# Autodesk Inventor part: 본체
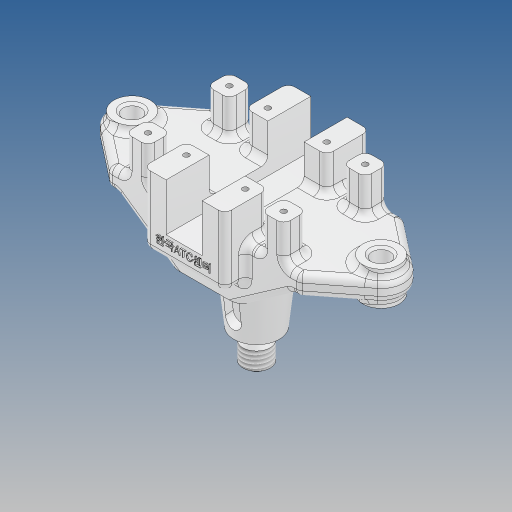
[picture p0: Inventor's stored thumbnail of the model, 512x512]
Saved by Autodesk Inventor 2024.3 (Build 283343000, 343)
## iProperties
Created: 2025-07
Part Number: 본체
Material: 알루미늄 6061
Document SubType Name: Modeling
Designer: user
Mass: 327.756 g
Surface Area: 261.455 cm^2
Volume: 121.391 cm^3
Density: 2.7 g/cm^3
Appearance: 알루미늄 - 평지
Author: user
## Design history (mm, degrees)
sketch "스케치1"
  geometry: L1 (-41.804, 23)-(41.804, 23); L2 (41.804, 23)-(41.804, -23); L3 (41.804, -23)-(-41.804, -23); L4 (-41.804, -23)-(-41.804, 23); L5 (-41.804, 23)-(41.804, -23); L6 (41.804, 23)-(-41.804, -23); L7 (41.804, -23)-(61.157, -7.88); L8 (41.804, 23)-(61.157, 7.88); L9 (0, -32.2)-(0, 32.2) reference; L10 (-41.804, -23)-(-61.157, -7.88); L11 (-41.804, 23)-(-61.157, 7.88); C1 r 10 at (55, 0); C2 r 8 at (55, 0); C3 r 8 at (-55, 0); A1 r 10 centre (-55, 0) between (-61.157, -7.88) and (-61.157, 7.88); 4 further points
  constraints: 20 end point, 4 centre point, 4 symmetric about line, 2 coincident, 2 midpoint, 2 parallel, 2 point on circle, 2 tangent, 1 horizontal, 1 horizontal alignment, 1 perpendicular, 1 other
  dimensions: "d0" = 110 distance of A1.centre C1.centre; "d1" = 46 distance between parallel lines of L1 L3; "d2" = 20 diameter of C1; "d3" = 76 deg angle of L8 L7; "d6" = 16 diameter of C2; "d7" = 16 diameter of C3
extrude "돌출1" new body sketch "스케치1" stored distance "d4" = 9; taper "d5" = 0 deg
extrude "돌출2" join sketch "스케치1" stored distance "d8" = 15; taper "d9" = 0 deg
sketch "스케치2"
  geometry: L1 (-41.804, -23)-(41.804, -23) reference; L2 (41.804, 23)-(-41.804, 23) reference; L3 (-30, 18)-(30, 18); L4 (30, 18)-(30, -18); L5 (30, -18)-(-30, -18); L6 (-30, -18)-(-30, 18); L7 (-30, 18)-(30, -18); L8 (30, 18)-(-30, -18); L9 (-35, 23)-(-25, 23); L10 (-25, 23)-(-25, 13); L11 (-25, 13)-(-35, 13); L12 (-35, 13)-(-35, 23); L13 (-35, 23)-(-25, 13); L14 (-25, 23)-(-35, 13); L15 (-35, -13)-(-25, -13); L16 (-25, -13)-(-25, -23); L17 (-25, -23)-(-35, -23); L18 (-35, -23)-(-35, -13); L19 (-35, -13)-(-25, -23); L20 (-25, -13)-(-35, -23); L21 (25, -13)-(35, -13); L22 (35, -13)-(35, -23); L23 (35, -23)-(25, -23); L24 (25, -23)-(25, -13); L25 (25, -13)-(35, -23); L26 (35, -13)-(25, -23); L27 (25, 23)-(35, 23); L28 (35, 23)-(35, 13); L29 (35, 13)-(25, 13); L30 (25, 13)-(25, 23); L31 (25, 23)-(35, 13); L32 (35, 23)-(25, 13); 7 further points
  constraints: 60 end point, 10 midpoint, 10 parallel, 5 horizontal, 5 perpendicular, 2 point on line
  dimensions: "d10" = 60 distance between parallel lines of L4 L6; "d11" = 36 distance between parallel lines of L5 L3; "d12" = 10 distance between parallel lines of L10 L12; "d13" = 10 distance between parallel lines of L11 L2; "d14" = 10 distance between parallel lines of L16 L18; "d15" = 10 distance between parallel lines of L22 L24; "d16" = 10 distance between parallel lines of L28 L30; "d17" = 10 distance between parallel lines of L27 L29
extrude "돌출3" join sketch "스케치2" distance "d18" = 16; taper "d19" = 0 deg
sketch "스케치3"
  geometry: L1 (6.804, 25)-(16.804, 25) reference; L2 (83.608, 0)-(0, 0) reference; L3 (41.804, -16)-(25.804, -16); L4 (41.804, 0)-(41.804, -16); L5 (25.804, -16)-(2.954, 0); L6 (2.954, 0)-(41.804, 0); L7 (57.804, -16)-(80.654, 0); L8 (0, 0)-(83.608, 0); L9 (41.804, -16)-(57.804, -16); 2 further points
  constraints: 14 end point, 4 symmetric about line, 2 point on line, 1 collinear, 1 horizontal, 1 midpoint, 1 vertical
  dimensions: "d20" = 145 deg angle of L3 L5; "d21" = 41 distance between parallel lines of L3 L1; "d22" = 16 distance from line of L4 L3.end
extrude "돌출4" join sketch "스케치3" stored distance "d23" = 16; taper "d24" = 0 deg
node "작업 평면1"
sketch "스케치4"
  geometry: L1 (-16.804, 9)-(-66.804, 9) reference; L2 (-59.804, 25)-(-23.804, 25); L3 (-23.804, 25)-(-23.804, -6); L4 (-23.804, -6)-(-59.804, -6); L5 (-59.804, -6)-(-59.804, 25); L6 (-59.804, 25)-(-23.804, -6); L7 (-23.804, 25)-(-59.804, -6); L8 (-57.804, -16)-(-25.804, -16) reference; 2 further points
  constraints: 12 end point, 2 parallel, 1 horizontal, 1 midpoint, 1 perpendicular, 1 vertical alignment
  dimensions: "d25" = 36 distance between parallel lines of L3 L5; "d26" = 31 distance between parallel lines of L4 L2; "d112" = 10 distance between parallel lines of L8 L4
extrude "돌출5" join sketch "스케치4" stored distance "d27" = 64; taper "d28" = 0 deg
sketch "스케치5"
  geometry: L1 (-23.804, 25)-(-59.804, 25) reference; L2 (-49.804, 25)-(-33.804, 25); L3 (-33.804, 25)-(-33.804, 4); L4 (-33.804, 4)-(-49.804, 4); L5 (-49.804, 4)-(-49.804, 25); 3 further points
  constraints: 8 end point, 2 midpoint, 2 parallel, 1 horizontal, 1 perpendicular, 1 point on line
  dimensions: "d29" = 16 distance between parallel lines of L3 L5; "d30" = 21 distance between parallel lines of L4 L1
extrude "돌출6" cut sketch "스케치5" distance "d31" = 64; taper "d32" = 0 deg
sketch "스케치6"
  geometry: L1 (0, 31)-(-64, 31) reference; L2 (-9, 15)-(-55, 15) reference; L3 (-45, 31)-(-19, 31); L4 (-19, 31)-(-19, 15); L5 (-19, 15)-(-45, 15); L6 (-45, 15)-(-45, 31); 5 further points
  constraints: 8 end point, 2 midpoint, 2 parallel, 2 point on line, 1 coincident, 1 horizontal, 1 perpendicular
  dimensions: "d33" = 26 distance between parallel lines of L4 L6
extrude "돌출7" cut sketch "스케치6" stored distance "d34" = 64; taper "d35" = 0 deg
sketch "스케치7"
  geometry: C1 r 12.5 at (16, -23); 1 further point
  constraints: 1 centre point, 1 coincident
  dimensions: "d36" = 25 diameter of C1
extrude "돌출8" join sketch "스케치7" distance "d37" = 4; taper "d38" = 0 deg
sketch "스케치8"
  geometry: L1 (-12.5, -24.5)-(12.5, -24.5) reference; L2 (0, -24.5)-(0, -47.5); L3 (0, -47.5)-(-10, -47.5); L4 (-10, -47.5)-(-12.5, -24.5); 1 further point
  constraints: 6 end point, 1 midpoint, 1 perpendicular, 1 vertical
  dimensions: "d39" = 23 distance between parallel lines of L1 L3; "d41" = 20 diameter of L3.end L2
revolve "회전1" sketch "스케치8" stored, may be unused: angle "d42" = 360 deg
sketch "스케치9"
  geometry: C1 r 10 at (0, 0) reference; C2 r 4.7 at (0, 0)
  constraints: 1 centre point, 1 coincident
  dimensions: "d43" = 9.4 diameter of C2
extrude "돌출9" join sketch "스케치9" distance "d44" = 3; taper "d45" = 0 deg
sketch "스케치11"
  geometry: L1 (-4.7, -50.5)-(4.7, -50.5) reference; L2 (-4.7, -50.5)-(-6, -52.752); L3 (0, -61.5)-(0, -50.5); L4 (-6, -52.752)-(-6, -61.5); L5 (-6, -61.5)-(0, -61.5); 1 further point
  constraints: 8 end point, 1 midpoint, 1 perpendicular, 1 vertical, 1 vertical alignment
  dimensions: "d50" = 30 deg angle of L3 L2; "d53" = 12 diameter of L4 L3; "d54" = 11 distance between parallel lines of L1 L5
revolve "회전2" sketch "스케치11" stored, may be unused: angle "d55" = 90 deg
feature "스레드1" dims "d56" = 8.748, "d57" = 0
sketch "스케치14"
  geometry: C1 r 8 at (0, 0) reference; C2 r 8 at (110, 0) reference; 3 further points
  constraints: 2 coincident
hole "구멍1" sketch "스케치14" at (0, 0), (110, 0) diameter "d62" = 8; stored, may be unused: countersink angle "d66" = 90 deg, drill point angle "d68" = 118 deg; dims "d63" = 6, "d64" = 4, "d65" = 2, "d67" = 8
sketch "스케치15"
  geometry: L1 (-30, 18)-(30, 18); L2 (30, 18)-(30, -18); L3 (30, -18)-(-30, -18); L4 (-30, -18)-(-30, 18); L5 (-30, 18)-(30, -18); L6 (30, 18)-(-30, -18); L7 (-13, 18)-(13, 18); L8 (13, 18)-(13, -18); L9 (13, -18)-(-13, -18); L10 (-13, -18)-(-13, 18); L11 (-13, 18)-(13, -18); L12 (13, 18)-(-13, -18); 2 further points
  constraints: 24 end point, 4 midpoint, 4 parallel, 2 horizontal, 2 perpendicular, 1 coincident, 1 point on line
  dimensions: "d76" = 60 distance between parallel lines of L2 L4; "d77" = 36 distance between parallel lines of L3 L1; "d78" = 26 distance between parallel lines of L8 L10
hole "구멍2" sketch "스케치15" at (-30, 18), (-30, -18), (-13, -18), (13, -18), (30, -18), (30, 18), (13, 18), (-13, 18) diameter "d69" = 2.459; stored, may be unused: countersink angle "d73" = 90 deg, drill point angle "d75" = 118 deg; dims "d70" = 6, "d71" = 4, "d72" = 2, "d74" = 8
node "작업 평면2"
sketch "스케치17"
  geometry: L1 (19.5, -14)-(22, -37) reference; L2 (20.217, -20.597)-(24.194, -20.164); L3 (24.194, -20.164)-(23.815, -16.685); L4 (23.815, -16.685)-(19.839, -17.117); L5 (20.217, -20.597)-(19.839, -17.117); L6 (21.19, -29.544)-(25.166, -29.112); L7 (21.568, -33.023)-(25.544, -32.591); L8 (25.544, -32.591)-(25.166, -29.112); L9 (22, -37)-(42, -37) reference; 1 further point
  constraints: 14 end point, 6 perpendicular, 4 point on line, 1 collinear
  dimensions: "d79" = 7 diameter of L4 L2; "d80" = 7 diameter of L7 L6; "d81" = 16 distance between parallel lines of L7 L4; "d82" = 4 distance between parallel lines of L1 L3; "d83" = 4 distance between parallel lines of L1 L8; "d120" = 4 distance of L1.end L7.start
revolve "회전4" stored, may be unused: angle "d85" = 90 deg
revolve "회전5" stored, may be unused: angle "d86" = 90 deg
sketch "스케치18"
  geometry: L1 (20.217, -20.597)-(24.194, -20.164) reference; L2 (21.19, -29.544)-(25.166, -29.112) reference; L3 (19.5, -14)-(22, -37) reference; L4 (24.194, -20.164)-(25.166, -29.112); L5 (25.166, -29.112)-(21.19, -29.544); L6 (20.217, -20.597)-(21.19, -29.544); L7 (24.194, -20.164)-(20.217, -20.597); 1 further point
  constraints: 8 end point, 1 collinear, 1 perpendicular
extrude "돌출11" cut sketch "스케치18" stored distance "d87" = 7; taper "d88" = 0 deg
sketch "스케치19"
  geometry: L1 (-49.804, 25)-(-59.804, 25) reference; 2 further points
  constraints: 1 vertical alignment, 1 other
  dimensions: "d89" = 24 distance from line of L1 point (-41.804, 1)
fillet "모깎기1" dims "d90" = 3
fillet "모깎기2" dims "d91" = 3
fillet "모깎기3" dims "d92" = 3
fillet "모깎기4" dims "d93" = 3
fillet "모깎기5" dims "d94" = 3
fillet "모깎기6" dims "d95" = 3
fillet "모깎기7" dims "d96" = 3
fillet "모깎기8" dims "d97" = 3
fillet "모깎기9" dims "d98" = 3
fillet "모깎기10" dims "d99" = 3
fillet "모깎기12" dims "d101" = 3
fillet "모깎기13" dims "d102" = 3
fillet "모깎기14" dims "d103" = 3
fillet "모깎기16" dims "d105" = 3
fillet "모깎기17" dims "d106" = 3
fillet "모깎기18" dims "d107" = 3
fillet "모깎기19" dims "d108" = 3
fillet "모깎기20" dims "d109" = 3
feature "엠보싱1" dims "d110" = 0.5, "d111" = 0
node "작업 평면3"
sketch "스케치20"
  geometry: L1 (-22, -82)-(-34, -82) reference; L2 (-28, -20.5)-(-28, -82); L3 (-28, -82)-(-23.3, -82); L4 (-22, -81)-(-23.3, -82); L5 (-22, -81)-(-28, -81); L6 (-22, -82)-(-22, -73.252) reference
  constraints: 8 end point, 3 point on line, 1 midpoint, 1 perpendicular
  dimensions: "d113" = 9.4 diameter of L3.end L2; "d114" = 1 distance between parallel lines of L1 L5
sketch "스케치21"
  geometry: L1 (-22, -81)-(-28, -81) reference; L2 (-28, -20.5)-(-28, -82) reference; L3 (-34, -82)-(-34, -73.252) reference; L4 (-22, -81)-(-34, -81); L5 (-34, -81)-(-34, -88); L6 (-34, -88)-(-22, -88); L7 (-22, -88)-(-22, -81); 4 further points
  constraints: 8 end point, 2 parallel, 1 horizontal, 1 perpendicular
  dimensions: "d115" = 7 distance between parallel lines of L6 L1; "d116" = 12 distance between parallel lines of L5 L7
extrude "돌출12" cut sketch "스케치21" stored distance "d117" = 16; taper "d118" = 0 deg
revolve "회전6" stored, may be unused: angle "d119" = 90 deg
chamfer "모따기1" distance "d121" = 1; stored, may be unused: second distance "d122" = 2, angle "d123" = 45 deg
feature "ظ耀غ耀ؼ耀ؾ耀ـ耀ق耀ل耀ن耀" dims "d0" = 110, "d1" = 46, "d2" = 20, "d3" = 76 deg, "d4" = 9, "d5" = 0, "d6" = 16, "d7" = 16, "d8" = 15, "d9" = 0, "d10" = 60, "d11" = 36, "d12" = 10, "d13" = 10, "d14" = 10, "d15" = 10, "d16" = 10, "d17" = 10, "d18" = 16, "d19" = 0, "d20" = 145 deg, "d21" = 41, "d22" = 16, "d23" = 16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
node "솔리드1"
feature "A9D066F2-1C7D-4E18-AEED-F7BC21143FA4" dims "d56" = 8.748, "d57" = 0
